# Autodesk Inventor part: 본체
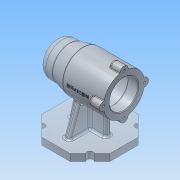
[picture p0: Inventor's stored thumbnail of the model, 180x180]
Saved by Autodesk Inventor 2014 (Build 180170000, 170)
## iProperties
Created: 2021-01
Part Number: 본체
Material: 알루미늄 6061
Document SubType Name: Modeling
Designer: NET
Density: 2.71 g/cm^3
Appearance: 알루미늄 - 평지
Mass: 632.295 g
Surface Area: 613.777 cm^2
Volume: 233.319 cm^3
Author: NET
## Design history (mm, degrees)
sketch "스케치1"
  geometry: L1 (20.711, 50)-(50, 20.711); L2 (50, 20.711)-(50, -20.711); L3 (50, -20.711)-(20.711, -50); L4 (20.711, -50)-(-20.711, -50); L5 (-20.711, -50)-(-50, -20.711); L6 (-50, -20.711)-(-50, 20.711); L7 (-50, 20.711)-(-20.711, 50); L8 (-20.711, 50)-(20.711, 50); L9 (-35.355, 35.355)-(35.355, -35.355); L10 (35.355, 35.355)-(-35.355, -35.355); L11 (-83.894, 0)-(83.894, 0); C1 r 4.5 at (-35.355, 35.355); C2 r 4.5 at (35.355, 35.355); C3 r 4.5 at (35.355, -35.355); C4 r 4.5 at (-35.355, -35.355); A1 r 50 centre (0, 0) between (0, 50) and (-35.355, -35.355); 3 further points
  constraints: 22 end point, 9 midpoint, 5 centre point, 4 coincident, 4 point on circle, 3 equal radius, 1 parallel, 1 vertical alignment, 17 other
  dimensions: "d0" = 100 diameter of A1; "d1" = 50 distance from line of point (0, 0) L2 (derived); "d2" = 9 diameter of C1; "d3" = 45 deg angle of L11 L9 (derived); "d4" = 45 deg angle of L10 L11 (derived)
extrude "돌출1" new body sketch "스케치1" distance "d5" = 10; taper "d6" = 0 deg
extrude "돌출2" cut sketch "스케치1" distance "d7" = 10; taper "d8" = 0 deg
sketch "스케치2"
  geometry: L1 (-71.975, 75)-(71.964, 75); L2 (-50, 75)-(-50, 105); L3 (-50, 105)-(10, 105); L4 (10, 105)-(30, 100); L5 (30, 100)-(50, 100); L6 (50, 100)-(50, 75); L7 (-50, 75)-(50, 75); 4 further points
  constraints: 14 end point, 3 perpendicular, 2 parallel, 2 vertical alignment, 1 horizontal, 1 midpoint, 1 point on line
  dimensions: "d9" = 75 distance from line of point (0, 0) L1; "d10" = 20 distance from line of L4.end L6; "d11" = 40 distance from line of L6 L3.end; "d12" = 100 distance between parallel lines of L2 L6 (derived); "d13" = 30 distance between parallel lines of L1 L3; "d14" = 25 distance between parallel lines of L1 L5
revolve "회전1" sketch "스케치2" stored, may be unused: angle "d15" = 90 deg
sketch "스케치3"
  geometry: C1 r 30 at (0, 0) reference; C2 r 21 at (0, 0); 1 further point
  constraints: 1 centre point, 1 coincident
  dimensions: "d16" = 42 diameter of C2
extrude "돌출3" cut sketch "스케치3" distance "d17" = 15; taper "d18" = 0 deg
sketch "스케치4"
  geometry: C1 r 21 at (0, 0) reference; C2 r 24 at (0, 0); 1 further point
  constraints: 1 centre point, 1 coincident
  dimensions: "d19" = 48 diameter of C2
extrude "돌출4" cut sketch "스케치4" distance "d20" = 42; taper "d21" = 0 deg
sketch "스케치5"
  geometry: C1 r 24 at (0, 0) reference; C2 r 21 at (0, 0); 1 further point
  constraints: 1 centre point, 1 coincident
  dimensions: "d22" = 42 diameter of C2
extrude "돌출5" cut sketch "스케치5" distance "d23" = 12; taper "d24" = 0 deg
sketch "스케치6"
  geometry: C1 r 21 at (0, 0) reference; C2 r 17.5 at (0, 0); 1 further point
  constraints: 1 centre point, 1 coincident
  dimensions: "d25" = 35 diameter of C2
extrude "돌출6" cut sketch "스케치6" distance "d26" = 18; taper "d27" = 0 deg
sketch "스케치7"
  geometry: C1 r 17.5 at (0, 0) reference; C2 r 16 at (0, 0); 1 further point
  constraints: 1 centre point, 1 coincident
  dimensions: "d28" = 32 diameter of C2
extrude "돌출7" cut sketch "스케치7" distance "d29" = 4; taper "d30" = 0 deg
sketch "스케치8"
  geometry: C1 r 16 at (0, 0) reference; C2 r 10.5 at (0, 0); 1 further point
  constraints: 1 centre point, 1 coincident
  dimensions: "d31" = 21 diameter of C2
extrude "돌출8" cut sketch "스케치8" distance "d32" = 3; taper "d33" = 0 deg
fillet "모깎기1" dims "d34" = 0.3
fillet "모깎기2" dims "d35" = 3
sketch "스케치9"
  geometry: C1 r 21 at (0, 0) reference; C2 r 6 at (-30, 0); C3 r 6 at (0, 30); C4 r 6 at (30, 0); C5 r 6 at (0, -30); A1 r 30 centre (0, 0) between (-30, 0) and (0, 30) reference; 1 further point
  constraints: 4 centre point, 4 point on circle, 3 equal radius, 2 horizontal alignment, 2 vertical alignment
  dimensions: "d37" = 6 radius of C3
extrude "돌출9" join sketch "스케치9" distance "d38" = 16; taper "d39" = 0 deg
sketch "스케치10"
  geometry: A1 r 6 centre (0, 0) between (-0.6, -5.97) and (-0.6, 5.97) reference; A2 r 6 centre (-30, 30) between (-24.03, 29.4) and (-35.97, 29.4) reference; A3 r 6 centre (-60, 0) between (-59.4, 5.97) and (-59.4, -5.97) reference; A4 r 6 centre (-30, -30) between (-35.97, -29.4) and (-24.03, -29.4) reference; 5 further points
  constraints: 4 coincident
hole "구멍1" sketch "스케치10" at (-30, 30), (-60, 0), (0, 0), (-30, -30) diameter "d40" = 3.242; stored, may be unused: countersink angle "d44" = 90 deg, drill point angle "d46" = 118 deg; dims "d41" = 8, "d42" = 4, "d43" = 2, "d45" = 10
fillet "모깎기3" dims "d47" = 3
fillet "모깎기4" dims "d48" = 10
chamfer "모따기1" distance "d49" = 1; stored, may be unused: second distance "d50" = 2, angle "d51" = 45 deg
sketch "스케치11"
  geometry: L1 (50, -20.711)-(50, 20.711) reference; L2 (27, 4)-(0, 4); L3 (0, 4)-(0, -4); L4 (0, -4)-(27, -4); L5 (27, -4)-(27, 4); 2 further points
  constraints: 8 end point, 2 parallel, 1 coincident, 1 horizontal, 1 midpoint, 1 perpendicular
  dimensions: "d52" = 8 distance between parallel lines of L4 L2; "d53" = 23 distance between parallel lines of L1 L5
extrude "돌출10" join sketch "스케치11" stored distance "d54" = 16; taper "d55" = 0 deg
sketch "스케치12"
  geometry: L1 (50, 0)-(-50, 0) reference; L2 (-50, 0)-(-50, 10) reference; L3 (-50, 10)-(-27, 10) reference; L4 (-27, 10)-(-27, 45) reference; L5 (-27, 45)-(-34, 45) reference; L6 (-34, 45)-(-34, 39) reference; L7 (-34, 39)-(-50, 39) reference; L8 (-50, 39)-(-50, 43.379) reference; L9 (-50, 43.379)-(-40, 43.379) reference; L10 (-40, 43.379)-(-39.026, 45) reference; L11 (-39.026, 45)-(-40, 46.621) reference; L12 (-40, 46.621)-(-50, 46.621) reference; L13 (-50, 46.621)-(-50, 53) reference; L14 (-50, 53)-(-49, 54) reference; L15 (-49, 54)-(-35, 54) reference; L16 (-32, 51)-(4, 51) reference; L17 (7, 54)-(18.7, 54) reference; L18 (19, 54.3)-(19, 57.5) reference; L19 (19, 57.5)-(36.7, 57.5) reference; L20 (37, 57.8)-(37, 59) reference; L21 (37, 59)-(40.7, 59) reference; L22 (41, 59.3)-(41, 64.5) reference; L23 (44, 67.5)-(44, 82.5) reference; L24 (41, 85.5)-(41, 90.7) reference; L25 (40.7, 91)-(37, 91) reference; L26 (37, 91)-(37, 92.2) reference; L27 (36.7, 92.5)-(19, 92.5) reference; L28 (19, 92.5)-(19, 95.7) reference; L29 (18.7, 96)-(7, 96) reference; L30 (4, 99)-(-32, 99) reference; L31 (-35, 96)-(-49, 96) reference; L32 (-49, 96)-(-50, 97) reference; L33 (-50, 97)-(-50, 103.379) reference; L34 (-50, 103.379)-(-40, 103.379) reference; L35 (-40, 103.379)-(-39.026, 105) reference; L36 (-39.026, 105)-(-40, 106.621) reference; L37 (-40, 106.621)-(-50, 106.621) reference; L38 (-50, 106.621)-(-50, 111) reference; L39 (-50, 111)-(-34, 111) reference; L40 (-34, 111)-(-34, 105) reference; L41 (-34, 105)-(9.631, 105) reference; L42 (10.358, 104.91)-(29.642, 100.09) reference; L43 (30.369, 100)-(40, 100) reference; L44 (50, 90)-(50, 60) reference; L45 (40, 50)-(30.369, 50) reference; L46 (29.642, 49.91)-(10.358, 45.09) reference; L47 (9.631, 45)-(0, 45) reference; L48 (0, 45)-(0, 10) reference; L49 (0, 10)-(50, 10) reference; L50 (50, 10)-(50, 0) reference; L51 (27, 10)-(19.724, 47.431); A1 r 3 centre (-32, 54) between (-35, 54) and (-32, 51) reference; A2 r 3 centre (4, 54) between (4, 51) and (7, 54) reference; A3 r 0.3 centre (18.7, 54.3) between (18.7, 54) and (19, 54.3) reference; A4 r 0.3 centre (36.7, 57.8) between (36.7, 57.5) and (37, 57.8) reference; A5 r 0.3 centre (40.7, 59.3) between (40.7, 59) and (41, 59.3) reference; A6 r 3 centre (41, 67.5) between (41, 64.5) and (44, 67.5) reference; A7 r 3 centre (41, 82.5) between (44, 82.5) and (41, 85.5) reference; A8 r 0.3 centre (40.7, 90.7) between (41, 90.7) and (40.7, 91) reference; A9 r 0.3 centre (36.7, 92.2) between (37, 92.2) and (36.7, 92.5) reference; A10 r 0.3 centre (18.7, 95.7) between (19, 95.7) and (18.7, 96) reference; A11 r 3 centre (4, 96) between (7, 96) and (4, 99) reference; A12 r 3 centre (-32, 96) between (-32, 99) and (-35, 96) reference; A13 r 3 centre (9.631, 102) between (10.358, 104.91) and (9.631, 105) reference; A14 r 3 centre (30.369, 103) between (29.642, 100.09) and (30.369, 100) reference; A15 r 10 centre (40, 90) between (50, 90) and (40, 100) reference; A16 r 10 centre (40, 60) between (40, 50) and (50, 60) reference; A17 r 3 centre (30.369, 47) between (30.369, 50) and (29.642, 49.91) reference; A18 r 3 centre (9.631, 48) between (9.631, 45) and (10.358, 45.09) reference; 1 further point
  constraints: 2 end point, 2 point on line
  dimensions: "d56" = 23 distance from line of L50 L51.start; "d57" = 101 deg angle of L49 L51
feature "리브1" sketch "스케치12" dims "d58" = 1, "d59" = 8, "d60" = 0, "d61" = 0, "d62" = 1, "d63" = 1
sketch "스케치13"
  geometry: L1 (-50, 10)-(-4, 10) reference; L2 (-4, 10)-(-4, 45.268) reference; L3 (4, 45.268)-(4, 10) reference; L4 (4, 10)-(50, 10) reference; L5 (50, 10)-(50, 0) reference; L6 (50, 0)-(-50, 0) reference; L7 (-50, 0)-(-50, 10) reference; L8 (-19.606, 52.293)-(-35, 10); L9 (19.606, 52.293)-(35, 10); C1 r 24 at (0, 75) reference; A1 r 30 centre (0, 75) between (4, 45.268) and (-4, 45.268) reference; 1 further point
  constraints: 4 end point, 2 point on circle, 2 point on line
  dimensions: "d64" = 15 distance from line of L7 L8.end; "d65" = 15 distance from line of L5 L9.end; "d66" = 110 deg angle of L4 L9; "d67" = 110 deg angle of L1 L8
  node "절단 모서리 투영2"
feature "리브2" dims "d68" = 1, "d69" = 8, "d70" = 0, "d71" = 0, "d72" = 1, "d73" = 1
feature "리브3" dims "d74" = 1, "d75" = 8, "d76" = 0, "d77" = 0, "d78" = 1, "d79" = 1
fillet "모깎기5" dims "d80" = 3
fillet "모깎기6" dims "d81" = 1
node "작업 평면1"
sketch "스케치14"
  geometry: L1 (30, 36)-(30, 30.171) reference; L2 (-70, -15)-(-70, 15) reference; L3 (-70, 0)-(32.232, 0); 2 further points
  constraints: 2 end point, 1 midpoint, 1 perpendicular, 1 point on line, 1 other
  dimensions: "d82" = 38 horizontal distance of L1.start point (-8, 0)
feature "엠보싱1" sketch "스케치14" dims "d83" = 0.5, "d84" = 0
fillet "모깎기7" dims "d85" = 3
fillet "모깎기8" dims "d86" = 3
node "솔리드1"
node "절단 모서리 투영1"
